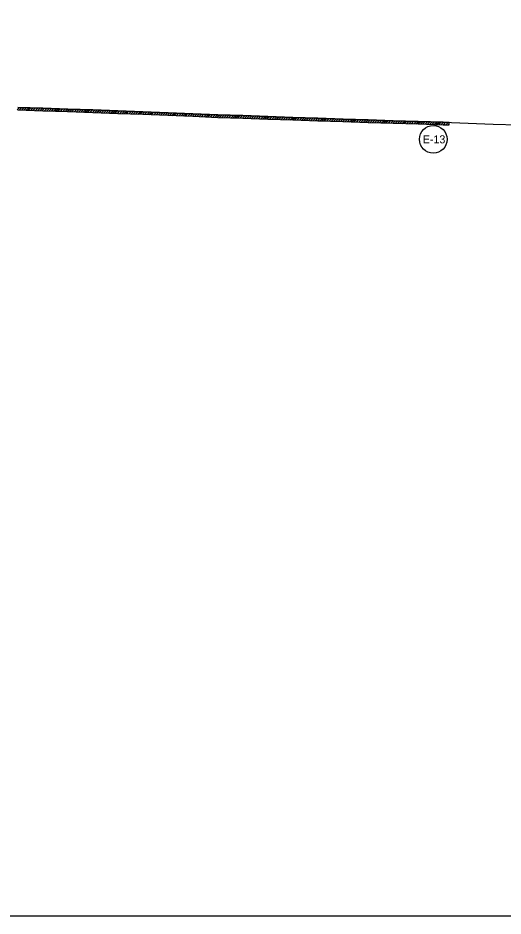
# Model space of a CAD drawing. Extents: x 976877 to 983987, y 1525984 to 1526526.
# Drawn here: x 978490 to 978781, y 1525984 to 1526522 of the extents above; entities that cross this region are included whole.
import ezdxf

# ---------------------------------------------------------------- set-up
doc = ezdxf.new("R2010")
doc.units = 0
doc.layers.add('R_Erosion', color=7, linetype='Continuous')
doc.layers.add('R_No Plot', color=7, linetype='Continuous')

msp = doc.modelspace()

# ---------------------------------------------------------------- linework, layer by layer
at = {"layer": 'R_Erosion'}
for p, q in [((978489.89, 1526467.24), (978491.34, 1526468.69)), ((978490.3, 1526467.23), (978505.29, 1526466.68)), ((978490.3, 1526467.23), (978505.29, 1526466.68)), ((978491.26, 1526467.19), (978492.71, 1526468.64)), ((978492.62, 1526467.14), (978494.07, 1526468.59)), ((978493.99, 1526467.09), (978495.44, 1526468.54)), ((978495.35, 1526467.04), (978496.8, 1526468.49)), ((978496.72, 1526466.99), (978498.17, 1526468.44)), ((978498.08, 1526466.94), (978499.53, 1526468.39)), ((978499.45, 1526466.89), (978500.9, 1526468.34)), ((978500.81, 1526466.84), (978502.26, 1526468.29)), ((978502.18, 1526466.79), (978503.62, 1526468.24)), ((978503.54, 1526466.74), (978504.99, 1526468.19)), ((978504.9, 1526466.7), (978506.36, 1526468.15)), ((978505.29, 1526466.68), (978520.29, 1526466.18)), ((978505.29, 1526466.68), (978520.29, 1526466.18)), ((978506.27, 1526466.65), (978507.72, 1526468.1)), ((978507.64, 1526466.6), (978509.09, 1526468.05)), ((978509.01, 1526466.56), (978510.46, 1526468.01)), ((978510.38, 1526466.51), (978511.83, 1526467.96)), ((978511.74, 1526466.46), (978513.2, 1526467.92)), ((978513.11, 1526466.42), (978514.56, 1526467.87)), ((978514.48, 1526466.37), (978515.93, 1526467.82)), ((978515.85, 1526466.33), (978517.3, 1526467.78)), ((978517.22, 1526466.28), (978518.67, 1526467.73)), ((978518.59, 1526466.23), (978520.04, 1526467.69)), ((978519.95, 1526466.19), (978521.41, 1526467.64)), ((978520.29, 1526466.18), (978535.28, 1526465.67)), ((978520.29, 1526466.18), (978535.28, 1526465.67)), ((978521.32, 1526466.14), (978522.77, 1526467.59)), ((978522.69, 1526466.1), (978524.14, 1526467.55)), ((978524.06, 1526466.05), (978525.51, 1526467.5)), ((978525.43, 1526466), (978526.88, 1526467.46)), ((978526.8, 1526465.96), (978528.25, 1526467.41)), ((978528.16, 1526465.91), (978529.62, 1526467.36)), ((978529.53, 1526465.87), (978530.98, 1526467.32)), ((978530.9, 1526465.82), (978532.35, 1526467.27)), ((978532.27, 1526465.77), (978533.72, 1526467.23)), ((978533.64, 1526465.73), (978535.09, 1526467.18)), ((978535.01, 1526465.68), (978536.45, 1526467.13)), ((978535.28, 1526465.67), (978550.26, 1526465.12)), ((978535.28, 1526465.67), (978550.26, 1526465.12)), ((978550.32, 1526466.62), (978535.33, 1526467.17)), ((978536.37, 1526465.63), (978537.82, 1526467.08)), ((978537.73, 1526465.58), (978539.18, 1526467.03)), ((978539.1, 1526465.53), (978540.55, 1526466.98)), ((978540.46, 1526465.48), (978541.91, 1526466.93)), ((978541.83, 1526465.43), (978543.27, 1526466.88)), ((978543.19, 1526465.38), (978544.64, 1526466.83)), ((978544.55, 1526465.33), (978546, 1526466.78)), ((978545.92, 1526465.28), (978547.36, 1526466.73)), ((978547.28, 1526465.23), (978548.73, 1526466.68)), ((978548.64, 1526465.18), (978550.09, 1526466.63)), ((978550.01, 1526465.13), (978551.45, 1526466.58)), ((978550.26, 1526465.12), (978565.25, 1526464.55)), ((978550.26, 1526465.12), (978565.25, 1526464.55)), ((978565.31, 1526466.05), (978550.32, 1526466.62)), ((978551.37, 1526465.08), (978552.82, 1526466.52)), ((978552.73, 1526465.03), (978554.18, 1526466.47)), ((978554.1, 1526464.97), (978555.54, 1526466.42)), ((978555.46, 1526464.92), (978556.91, 1526466.37)), ((978556.82, 1526464.87), (978558.27, 1526466.32)), ((978558.18, 1526464.82), (978559.63, 1526466.27)), ((978559.55, 1526464.77), (978560.99, 1526466.21)), ((978560.91, 1526464.72), (978562.36, 1526466.16)), ((978562.27, 1526464.67), (978563.72, 1526466.11)), ((978563.64, 1526464.61), (978565.08, 1526466.06)), ((978565, 1526464.56), (978566.44, 1526466.01)), ((978565.25, 1526464.55), (978580.24, 1526463.96)), ((978565.25, 1526464.55), (978580.24, 1526463.96)), ((978580.29, 1526465.46), (978565.31, 1526466.05)), ((978566.36, 1526464.51), (978567.8, 1526465.95)), ((978567.72, 1526464.46), (978569.16, 1526465.9)), ((978569.08, 1526464.4), (978570.52, 1526465.85)), ((978570.44, 1526464.35), (978571.89, 1526465.79)), ((978571.8, 1526464.3), (978573.25, 1526465.74)), ((978573.16, 1526464.24), (978574.61, 1526465.69)), ((978574.52, 1526464.19), (978575.97, 1526465.63)), ((978575.88, 1526464.14), (978577.33, 1526465.58)), ((978577.25, 1526464.08), (978578.69, 1526465.53)), ((978578.61, 1526464.03), (978580.05, 1526465.47)), ((978579.97, 1526463.97), (978581.41, 1526465.42)), ((978581.33, 1526463.92), (978582.77, 1526465.36)), ((978582.68, 1526463.86), (978584.13, 1526465.31)), ((978584.04, 1526463.81), (978585.48, 1526465.25)), ((978585.4, 1526463.75), (978586.84, 1526465.19)), ((978586.76, 1526463.7), (978588.2, 1526465.14)), ((978588.12, 1526463.64), (978589.56, 1526465.08)), ((978589.47, 1526463.58), (978590.92, 1526465.03)), ((978590.83, 1526463.53), (978592.27, 1526464.97)), ((978592.19, 1526463.47), (978593.63, 1526464.91)), ((978593.55, 1526463.42), (978594.99, 1526464.86)), ((978594.91, 1526463.36), (978596.35, 1526464.8)), ((978596.27, 1526463.3), (978597.71, 1526464.75)), ((978597.63, 1526463.25), (978599.07, 1526464.69)), ((978598.98, 1526463.19), (978600.43, 1526464.64)), ((978600.34, 1526463.14), (978601.79, 1526464.58)), ((978601.7, 1526463.08), (978603.14, 1526464.53)), ((978603.06, 1526463.03), (978604.5, 1526464.47)), ((978604.42, 1526462.97), (978605.86, 1526464.41)), ((978605.78, 1526462.92), (978607.22, 1526464.36)), ((978607.14, 1526462.86), (978608.58, 1526464.3)), ((978608.5, 1526462.81), (978609.94, 1526464.25)), ((978609.85, 1526462.75), (978611.31, 1526464.2)), ((978611.22, 1526462.7), (978612.68, 1526464.16)), ((978612.59, 1526462.66), (978614.05, 1526464.11)), ((978613.96, 1526462.62), (978615.42, 1526464.07)), ((978580.24, 1526463.96), (978595.19, 1526463.35)), ((978580.24, 1526463.96), (978595.19, 1526463.35)), ((978595.19, 1526463.35), (978610.18, 1526462.74)), ((978595.19, 1526463.35), (978610.18, 1526462.74)), ((978610.19, 1526462.74), (978625.18, 1526462.26)), ((978610.19, 1526462.74), (978625.18, 1526462.26)), ((978615.33, 1526462.57), (978616.79, 1526464.03)), ((978616.7, 1526462.53), (978618.16, 1526463.98)), ((978618.08, 1526462.49), (978619.53, 1526463.94)), ((978619.45, 1526462.44), (978620.9, 1526463.9)), ((978620.82, 1526462.4), (978622.27, 1526463.85)), ((978622.19, 1526462.35), (978623.64, 1526463.81)), ((978623.56, 1526462.31), (978625.01, 1526463.77)), ((978624.93, 1526462.27), (978626.38, 1526463.72)), ((978625.18, 1526462.26), (978640.17, 1526461.74)), ((978625.18, 1526462.26), (978640.17, 1526461.74)), ((978640.22, 1526463.24), (978625.23, 1526463.76)), ((978626.3, 1526462.22), (978627.75, 1526463.67)), ((978627.66, 1526462.17), (978629.11, 1526463.62)), ((978629.03, 1526462.13), (978630.48, 1526463.58)), ((978630.4, 1526462.08), (978631.85, 1526463.53)), ((978631.76, 1526462.03), (978633.21, 1526463.48)), ((978633.13, 1526461.98), (978634.58, 1526463.43)), ((978634.5, 1526461.94), (978635.95, 1526463.39)), ((978635.86, 1526461.89), (978637.31, 1526463.34)), ((978637.23, 1526461.84), (978638.68, 1526463.29)), ((978638.6, 1526461.8), (978640.05, 1526463.25)), ((978639.97, 1526461.75), (978641.41, 1526463.2)), ((978640.17, 1526461.74), (978655.16, 1526461.19)), ((978640.17, 1526461.74), (978655.16, 1526461.19)), ((978641.33, 1526461.7), (978642.78, 1526463.15)), ((978642.69, 1526461.65), (978644.14, 1526463.1)), ((978644.06, 1526461.6), (978645.51, 1526463.05)), ((978645.42, 1526461.55), (978646.87, 1526463)), ((978646.79, 1526461.5), (978648.24, 1526462.95)), ((978648.15, 1526461.45), (978649.6, 1526462.9)), ((978649.52, 1526461.4), (978650.96, 1526462.85)), ((978650.88, 1526461.35), (978652.33, 1526462.8)), ((978652.24, 1526461.3), (978653.69, 1526462.75)), ((978653.61, 1526461.25), (978655.06, 1526462.7)), ((978654.97, 1526461.2), (978656.43, 1526462.65)), ((978655.16, 1526461.19), (978670.16, 1526460.69)), ((978655.16, 1526461.19), (978670.16, 1526460.69)), ((978656.34, 1526461.15), (978657.79, 1526462.61)), ((978657.71, 1526461.11), (978659.16, 1526462.56)), ((978659.08, 1526461.06), (978660.53, 1526462.51)), ((978660.45, 1526461.02), (978661.9, 1526462.47)), ((978661.82, 1526460.97), (978663.27, 1526462.42)), ((978663.18, 1526460.93), (978664.64, 1526462.38)), ((978664.55, 1526460.88), (978666.01, 1526462.33)), ((978665.92, 1526460.83), (978667.37, 1526462.29)), ((978667.29, 1526460.79), (978668.74, 1526462.24)), ((978668.66, 1526460.74), (978670.11, 1526462.2)), ((978670.03, 1526460.7), (978671.48, 1526462.15)), ((978670.16, 1526460.69), (978685.2, 1526460.19)), ((978670.16, 1526460.69), (978685.2, 1526460.19)), ((978671.4, 1526460.65), (978672.85, 1526462.1)), ((978672.76, 1526460.61), (978674.22, 1526462.06)), ((978674.13, 1526460.56), (978675.59, 1526462.01)), ((978675.5, 1526460.52), (978676.96, 1526461.97)), ((978676.87, 1526460.47), (978678.32, 1526461.92)), ((978678.24, 1526460.43), (978679.69, 1526461.88)), ((978679.61, 1526460.38), (978681.06, 1526461.83)), ((978680.98, 1526460.33), (978682.43, 1526461.79)), ((978682.35, 1526460.29), (978683.8, 1526461.74)), ((978683.72, 1526460.24), (978685.17, 1526461.7)), ((978685.08, 1526460.2), (978686.54, 1526461.65)), ((978685.2, 1526460.19), (978700.19, 1526459.71)), ((978685.2, 1526460.19), (978700.2, 1526459.71)), ((978686.45, 1526460.15), (978687.91, 1526461.61)), ((978687.82, 1526460.11), (978689.28, 1526461.56)), ((978689.19, 1526460.07), (978690.65, 1526461.52)), ((978690.56, 1526460.02), (978692.02, 1526461.47)), ((978691.93, 1526459.98), (978693.39, 1526461.43)), ((978693.3, 1526459.93), (978694.76, 1526461.39)), ((978694.67, 1526459.89), (978696.13, 1526461.34)), ((978696.04, 1526459.84), (978697.5, 1526461.3)), ((978697.41, 1526459.8), (978698.87, 1526461.25)), ((978698.78, 1526459.75), (978700.24, 1526461.21)), ((978700.15, 1526459.71), (978701.61, 1526461.16)), ((978700.2, 1526459.71), (978715.19, 1526459.23)), ((978700.2, 1526459.71), (978715.19, 1526459.23)), ((978701.52, 1526459.67), (978702.98, 1526461.12)), ((978702.89, 1526459.62), (978704.35, 1526461.08)), ((978704.26, 1526459.58), (978705.72, 1526461.03)), ((978705.64, 1526459.54), (978707.09, 1526460.99)), ((978707.01, 1526459.49), (978708.46, 1526460.95)), ((978708.38, 1526459.45), (978709.83, 1526460.9)), ((978709.75, 1526459.4), (978711.2, 1526460.86)), ((978711.12, 1526459.36), (978712.57, 1526460.82)), ((978712.49, 1526459.32), (978713.94, 1526460.77)), ((978713.86, 1526459.27), (978715.31, 1526460.73)), ((978715.19, 1526459.23), (978730.18, 1526458.78)), ((978715.19, 1526459.23), (978730.18, 1526458.78)), ((978715.23, 1526459.23), (978716.69, 1526460.69)), ((978716.6, 1526459.19), (978718.06, 1526460.65)), ((978717.98, 1526459.15), (978719.43, 1526460.6)), ((978719.35, 1526459.11), (978720.8, 1526460.56)), ((978720.72, 1526459.07), (978722.18, 1526460.52)), ((978722.09, 1526459.02), (978723.55, 1526460.48)), ((978723.47, 1526458.98), (978724.92, 1526460.44)), ((978724.84, 1526458.94), (978726.3, 1526460.4)), ((978726.21, 1526458.9), (978727.67, 1526460.36)), ((978727.59, 1526458.86), (978729.04, 1526460.32)), ((978728.96, 1526458.82), (978730.42, 1526460.27)), ((978730.18, 1526458.78), (978745.17, 1526458.32)), ((978730.18, 1526458.78), (978745.17, 1526458.32)), ((978745.22, 1526459.82), (978730.23, 1526460.28)), ((978730.33, 1526458.78), (978731.79, 1526460.23)), ((978731.7, 1526458.73), (978733.16, 1526460.19)), ((978733.08, 1526458.69), (978734.53, 1526460.15)), ((978734.45, 1526458.65), (978735.9, 1526460.11)), ((978735.82, 1526458.61), (978737.28, 1526460.07)), ((978737.19, 1526458.57), (978738.65, 1526460.02)), ((978738.57, 1526458.53), (978740.02, 1526459.98)), ((978739.94, 1526458.48), (978741.39, 1526459.94)), ((978741.31, 1526458.44), (978742.77, 1526459.9)), ((978742.68, 1526458.4), (978744.14, 1526459.86)), ((978744.06, 1526458.36), (978745.51, 1526459.81)), ((978748.82, 1526459.7), (978745.22, 1526459.82)), ((978745.43, 1526458.31), (978746.88, 1526459.77)), ((978746.79, 1526458.27), (978748.24, 1526459.72)), ((978748.16, 1526458.22), (978748.79, 1526458.85)), ((978748.76, 1526458.2), (978748.82, 1526459.7)), ((978745.17, 1526458.32), (978748.76, 1526458.2)), ((978745.17, 1526458.32), (978748.76, 1526458.2))]:
    msp.add_line(p, q, dxfattribs=at)
for points in [[(978535.33, 1526467.17), (978520.34, 1526467.67), (978505.34, 1526468.18), (978490.36, 1526468.73)], [(978625.23, 1526463.76), (978610.24, 1526464.24), (978595.25, 1526464.85), (978580.3, 1526465.46)], [(978730.23, 1526460.28), (978715.23, 1526460.73), (978700.24, 1526461.21), (978685.25, 1526461.69), (978670.2, 1526462.19), (978655.21, 1526462.69), (978640.22, 1526463.24)]]:
    msp.add_lwpolyline(points, dxfattribs=at)
msp.add_circle((978739.32, 1526449.57), 8.26, dxfattribs=at)
for centre, start, end in [((978490.3, 1526467.23), 87.914, 88.0095), ((978505.34, 1526468.18), 267.914, 268.0706), ((978505.34, 1526468.18), 267.914, 268.0706), ((978520.34, 1526467.67), 268.0706, 268.0822), ((978535.28, 1526465.67), 87.8796, 88.0822), ((978550.26, 1526465.12), 87.8376, 87.8796), ((978565.25, 1526464.55), 87.7495, 87.8376), ((978580.24, 1526463.96), 87.6413, 87.7495), ((978595.25, 1526464.85), 267.6413, 267.6656), ((978610.24, 1526464.24), 267.6656, 268.1739), ((978610.24, 1526464.24), 267.6656, 268.1739), ((978625.18, 1526462.26), 88.021, 88.1739), ((978640.17, 1526461.74), 87.9063, 88.021), ((978655.21, 1526462.69), 267.9063, 268.0898), ((978655.21, 1526462.69), 267.9063, 268.0898), ((978670.2, 1526462.19), 268.0898, 268.1042), ((978685.25, 1526461.69), 268.1042, 268.1434), ((978700.24, 1526461.21), 268.1434, 268.1776), ((978715.23, 1526460.73), 268.1776, 268.277), ((978730.18, 1526458.78), 88.2541, 88.277), ((978745.17, 1526458.32), 88.0095, 88.2541)]:
    msp.add_arc(centre, 1.5, start, end, dxfattribs=at)
at = {"layer": 'R_No Plot'}
for points in [[(980109.47, 1526414.6), (980109.47, 1525984.07), (976876.91, 1525984.07), (976876.91, 1526522.3)], [(978490.35, 1526468.73), (978505.34, 1526468.18), (978520.34, 1526467.67), (978535.33, 1526467.17), (978550.32, 1526466.62), (978565.31, 1526466.05), (978580.3, 1526465.46), (978595.25, 1526464.85), (978610.24, 1526464.24), (978625.23, 1526463.76), (978640.22, 1526463.24), (978655.21, 1526462.69), (978670.2, 1526462.19), (978685.25, 1526461.69), (978700.24, 1526461.21), (978715.23, 1526460.73), (978730.23, 1526460.28), (978745.22, 1526459.82), (978760.21, 1526459.3), (978775.2, 1526458.73), (978790.2, 1526458.23)]]:
    msp.add_lwpolyline(points, dxfattribs=at)
msp.add_circle((978739.32, 1526449.57), 8.26, dxfattribs=at)

# ---------------------------------------------------------------- texts
at = {"layer": 'R_Erosion'}
msp.add_text('E-13', height=4.8, dxfattribs=at).set_placement((978732.99, 1526447.17))

doc.saveas('drawing.dxf')
